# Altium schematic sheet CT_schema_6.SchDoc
size 143 x 123 mm
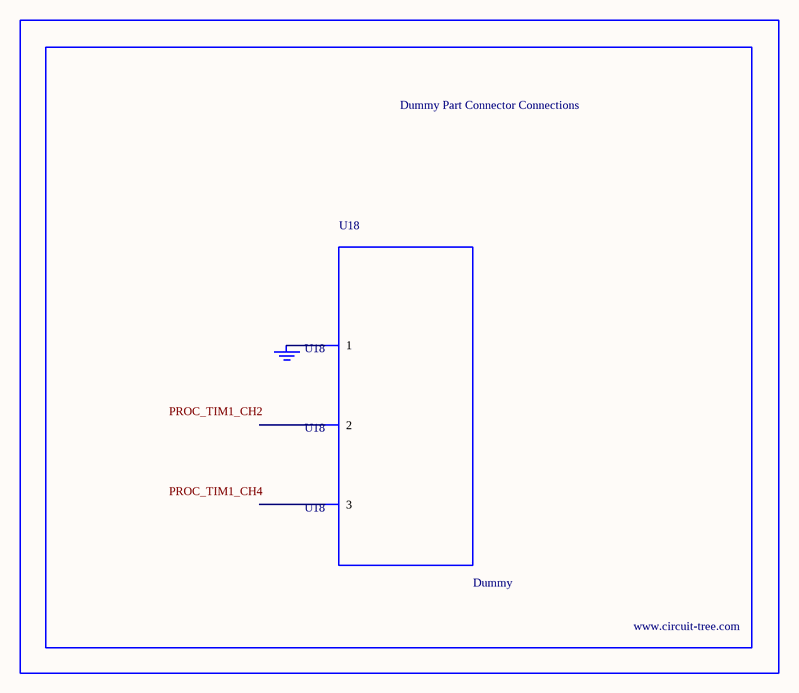
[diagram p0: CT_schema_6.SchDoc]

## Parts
BORDER5  (no value)
GND_INSTANCE_5_0  (no value)
U18  Dummy  [DUMMY_PACKAGE_172]

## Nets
NetGND_INSTANCE_5_0_0: GND_INSTANCE_5_0.0(GND) U18.1

Not connected (* = marked no-connect by the designer): U18 2 3

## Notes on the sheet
- Labels drawn without touching a wire or pin: PROC_TIM1_CH2, PROC_TIM1_CH4

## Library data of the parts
BORDER5 = BORDER_PAGE5
GND_INSTANCE_5_0 = GND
